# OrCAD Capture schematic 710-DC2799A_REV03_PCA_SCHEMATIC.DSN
size B; note: SPI Extender Over Differential Link
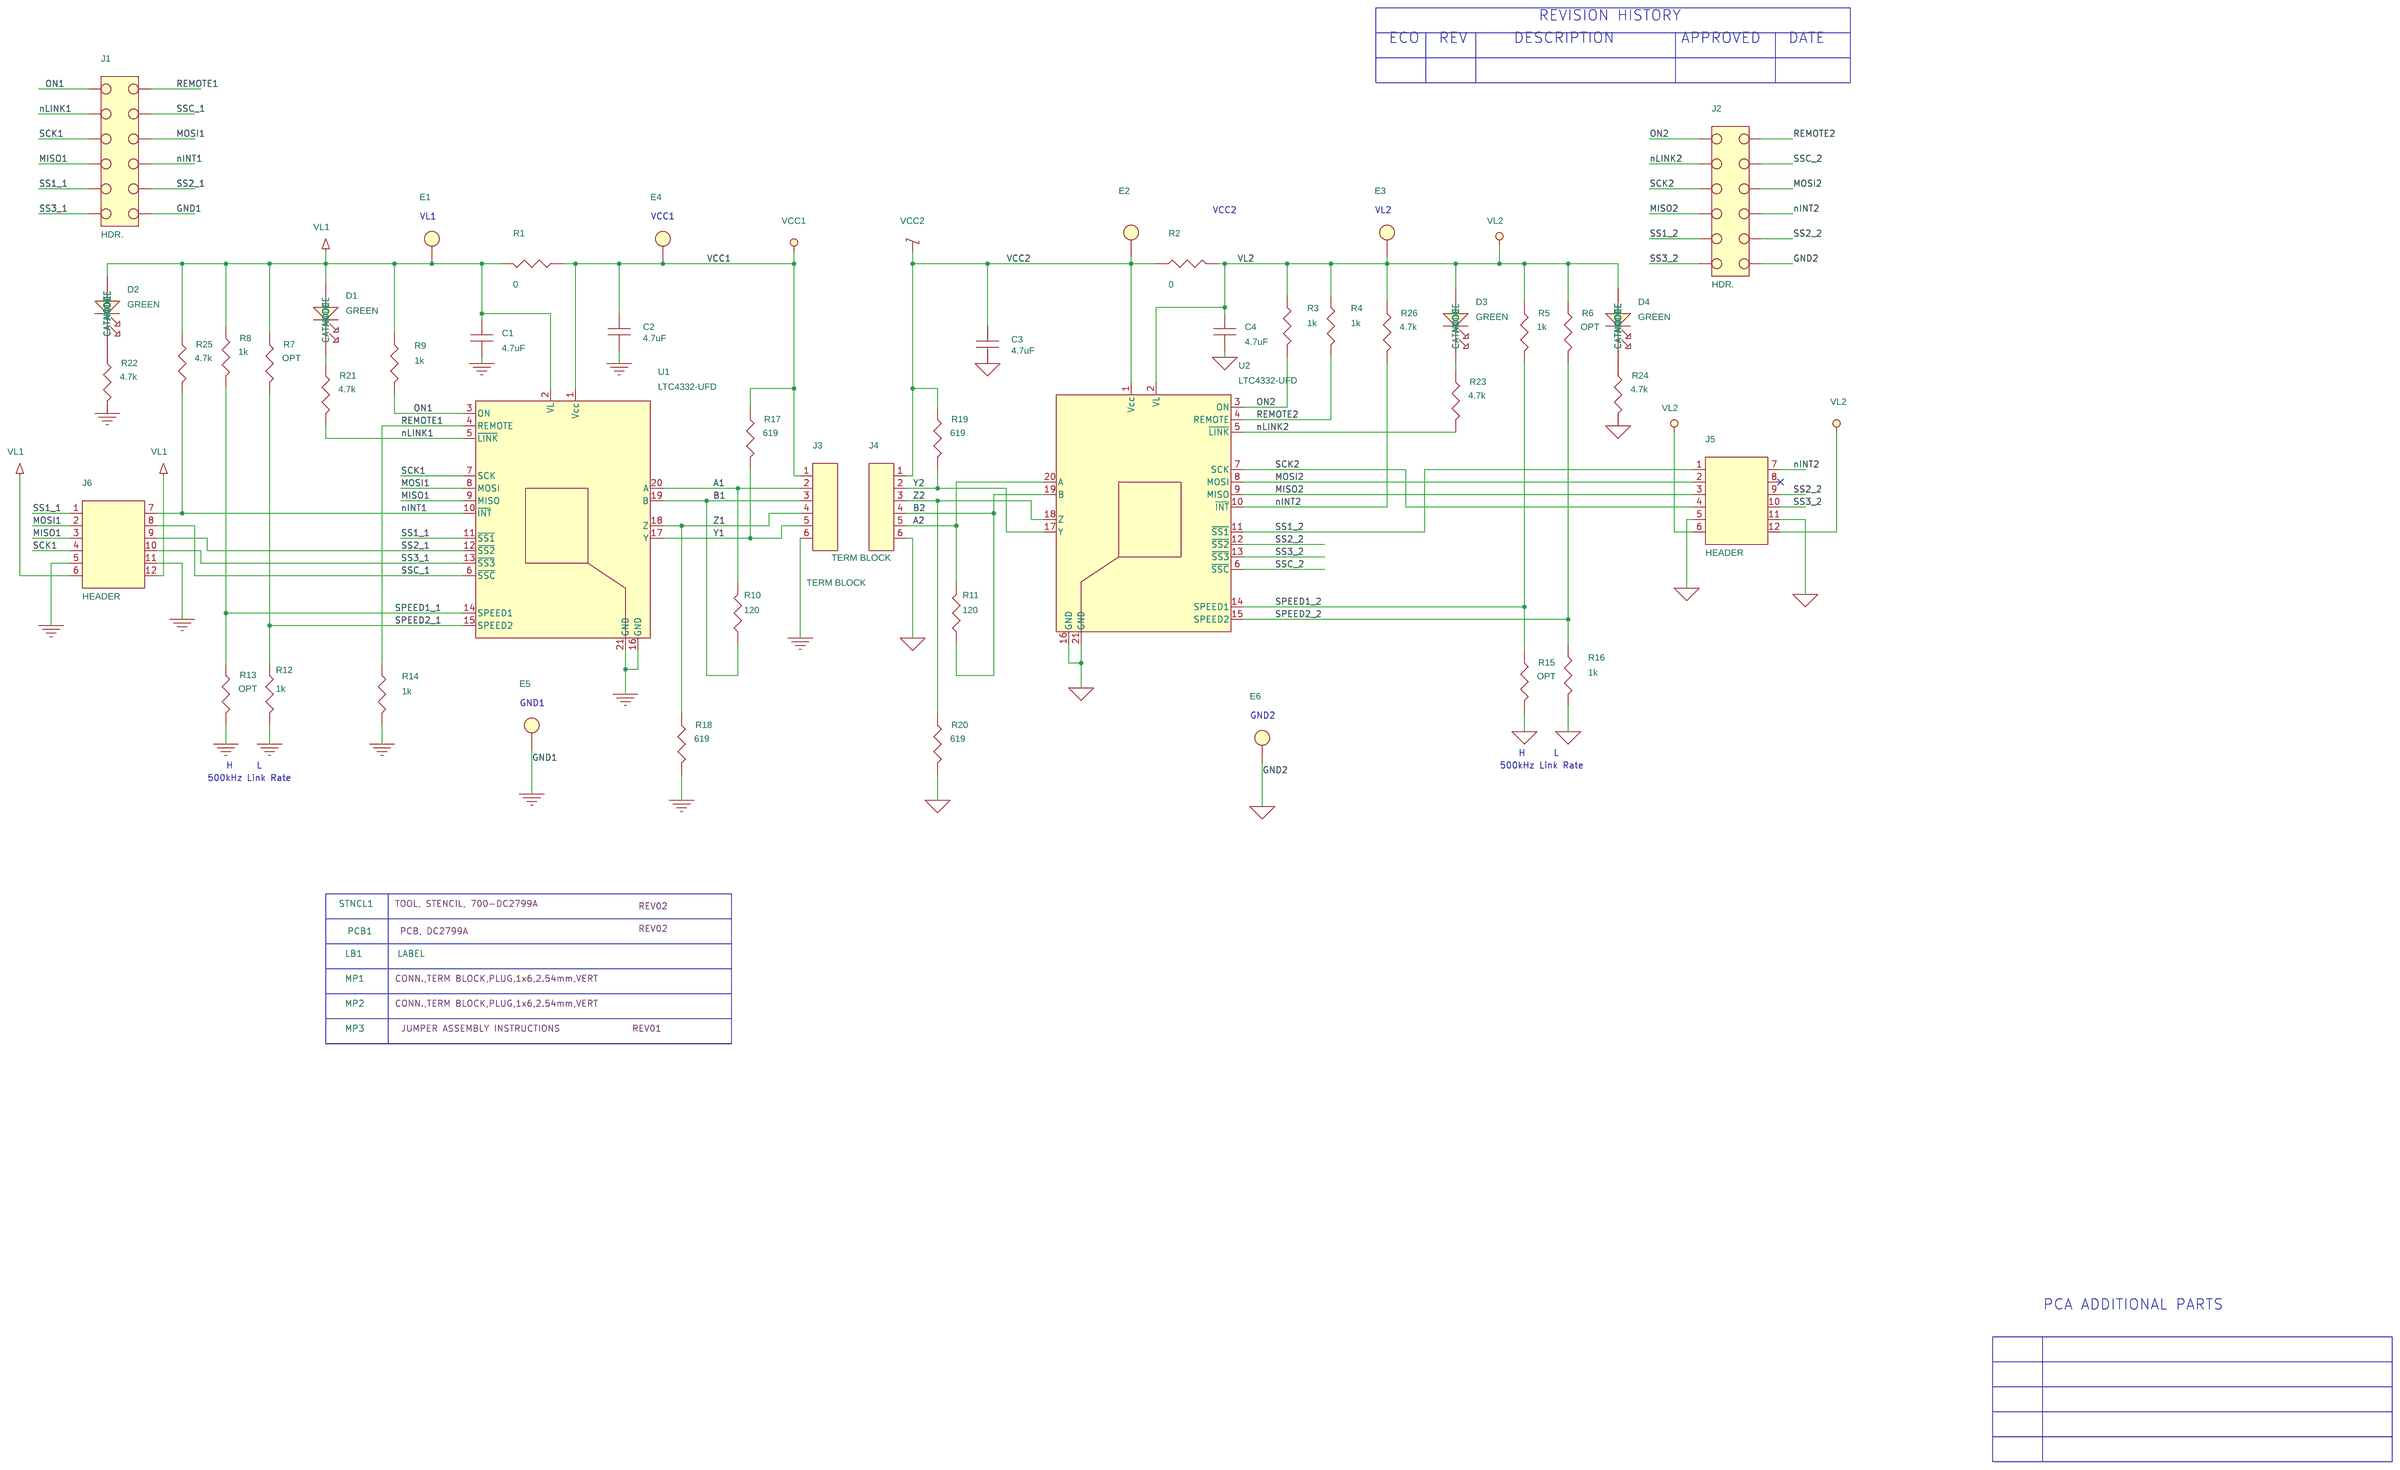
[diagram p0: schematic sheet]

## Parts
C1  4.7uF  [CC0603N]
C2  4.7uF  [CC0603N]
C3  4.7uF  [CC0603N]
C4  4.7uF  [CC0603N]
D1  GREEN  [LED_0603]
D2  GREEN  [LED_0603]
D3  GREEN  [LED_0603]
D4  GREEN  [LED_0603]
E1  TEST POINT  [MILLMAX2308]
E2  TEST POINT  [MILLMAX2308]
E3  TEST POINT  [MILLMAX2308]
E4  TEST POINT  [MILLMAX2308]
E5  TEST POINT  [MILLMAX2308]
E6  TEST POINT  [MILLMAX2308]
J1  HDR.  [HDR2X6-100-SM]
J2  HDR.  [HDR2X6-100-SM]
J3  TERM BLOCK  [WURTH-691382000006]
J4  TERM BLOCK  [WURTH-691382000006]
J5  HEADER  [WURTH-613012243121_PMOD]
J6  HEADER  [WURTH-61301221021_PMOD]
LB1  LABEL  [895-0154_REV01]
MP1  TERM BLOCK  [UNASSIGNED]
MP2  TERM BLOCK  [UNASSIGNED]
MP3  DOCUMENT
PCB1  PCB, DC2799A
R1  0  [CR0603N]
R2  0  [CR0603N]
R3  1k  [CR0805N]
R4  1k  [CR0805N]
R5  1k  [CR0805N]
R6  OPT  [CR0805N]
R7  OPT  [CR0805N]
R8  1k  [CR0805N]
R9  1k  [CR0805N]
R10  120  [CR0805N]
R11  120  [CR0805N]
R12  1k  [CR0805N]
R13  OPT  [CR0805N]
R14  1k  [CR0805N]
R15  OPT  [CR0805N]
R16  1k  [CR0805N]
R17  619  [CR0805N]
R18  619  [CR0805N]
R19  619  [CR0805N]
R20  619  [CR0805N]
R21  4.7k  [CR0603N]
R22  4.7k  [CR0603N]
R23  4.7k  [CR0603N]
R24  4.7k  [CR0603N]
R25  4.7k  [CR0603N]
R26  4.7k  [CR0603N]
STNCL1  TOOL, STENCIL, 700-DC2799A
U1  LTC4332-UFD  [LTC-UFD-20-1711]
U2  LTC4332-UFD  [LTC-UFD-20-1711]

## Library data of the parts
C1 C4 = CAP: CAP.,4.7uF,X5R,16V,20%,0603; CLASS: DISCRETE; Dielectric Type: X5R; FPLIST: CC0603N,CC0603L,CC0603M; Inventory Qty: 28841; Manufacturer: MURATA; Manufacturer PN: GRM188R61C475MAAJD; PART_NUMBER: 150-0551; Package Size: 0603; Rated Voltage: 16V; Tolerance: 20%
C2 C3 = CAP: CAP.,4.7uF,X5R,16V,20%,0603; CLASS: DISCRETE; Dielectric Type: X5R; FPLIST: CC0603N,CC0603L,CC0603M; Inventory Qty: 28841; Manufacturer: MURATA; Manufacturer PN: GRM188R61C475MAAJD; PART_NUMBER: 150-0551; Package Size: 0603; Rated Voltage: 16V; Tolerance: 20%; UserField01: AEC-Q200
D1-D4 = LED: LED,GREEN,WATERCLEAR,0603; CLASS: DISCRETE; Inventory Qty: 7311; Manufacturer: WURTH ELEKTRONIK; Manufacturer PN: 150060GS75000; PART_NUMBER: 270-0057; Package Type: 0603
E1-E6 = TEST_POINT_.156_MILL-MAX_2308: TEST POINT,TURRET,0.064" MTG. HOLE,PCB 0.062" THICK; CLASS: IO; Inventory Qty: 833448; Manufacturer: MILL-MAX; Manufacturer PN: 2308-2-00-80-00-00-07-0; PART_NUMBER: 260-0004
J1 J2 = HDR2X6: CONN.,HDR.,MALE,2x6,2.54mm,THT, STR; CLASS: IO; Inventory Qty: 1000; Manufacturer: SAMTEC; Manufacturer PN: TSW-106-07-S-D; PART_NUMBER: 250-0740
J3 J4 = CON6: CONN.,TERM BLOCK,HEADER,1x6,2.54mm,VERT; CLASS: IO; Inventory Qty: 0; Manufacturer: WURTH ELEKTRONIK; Manufacturer PN: 691382000006; PART_NUMBER: 250-0924
J5 = HDR2x6_PMOD: CONN.,HEADER,RECEPT,2x6,.100",2.54mm,TH,R/A; CLASS: IO; FPLIST: WURTH-613012243121,WURTH-613012243121_PMOD; Inventory Qty: 0; Manufacturer: Sullins Connector Solutions; Manufacturer PN: PPPC062LJBN-RC; Operating Temperature Minimum: -40C - 105C; PART_NUMBER: 250-0925
J6 = HDR2x6_PMOD: CONN.,HEADER,MALE,2x6,2.54mm,TH,R/A; CLASS: IO; FPLIST: WURTH-61301221021,WURTH-61301221021_PMOD; Inventory Qty: 0; Manufacturer: WURTH ELEKTRONIK; Manufacturer PN: 61301221021; Operating Temperature Minimum: -40C - 125C; PART_NUMBER: 250-0926
LB1 = BLANK_LABEL: LABEL SPEC, DEMO BOARD SERIAL NUMBER; Inventory Qty: 0; Manufacturer: BRADY; Manufacturer PN: THT-96-717-10; PART_NUMBER: 895-0154
MP1 MP2 = BLANK_PINLESS_MECHANICAL_PART: CONN.,TERM BLOCK,PLUG,1x6,2.54mm,VERT; CLASS: IO; Inventory Qty: 0; Manufacturer: WURTH ELEKTRONIK; Manufacturer PN: 691381000006; PART_NUMBER: 250-0923
MP3 = BLANK_PINLESS_MECHANICAL_PART: JUMPER ASSEMBLY INSTRUCTIONS; BOM Notes: REV01; CLASS: DISCRETE; Manufacturer: ANALOG DEVICES INC.; Manufacturer PN: 003-0102; PART_NUMBER: 003-0102
PCB1 = BLANK_PCB_PART: BOM Notes: REV02; CLASS: DISCRETE; Inventory Qty: 0; Manufacturer: EAGLE TECH. INC.; Manufacturer PN: 600-DC2799A; PART_NUMBER: 600-DC2799A
R1 R2 = RES: RES.,0 OHM,1/10W,0603,AEC-Q200; CLASS: DISCRETE; FPLIST: CR0603N,CR0603L,CR0603M; Inventory Qty: 642761; Manufacturer: VISHAY; Manufacturer PN: CRCW06030000Z0EA; PART_NUMBER: 100-0009; Package Size: 0603; Rated Power: 1/10W
R3-R5 R8 R9 R12 R14 R16 = RES: RES.,1k OHMS,1%,1/8W,0805,AEC-Q200; CLASS: DISCRETE; FPLIST: CR0805N,CR0805L,CR0805M; Inventory Qty: 20150; Manufacturer: PANASONIC; Manufacturer PN: ERJ-6ENF1001V; PART_NUMBER: 100-0761; Package Size: 0805; Rated Power: 1/8W; Temperature Coefficient: +/-100PPM; Tolerance: 1%
R6 R7 R13 R15 = RES: RES., OPTION, 0805; CLASS: DISCRETE; FPLIST: CR0805N,CR0805L,CR0805M; PART_NUMBER: 100-2558; Package Size: 0805
R10 R11 = RES: RES.,120 OHMS,5%,1/8W,0805,AEC-Q200; CLASS: DISCRETE; FPLIST: CR0805N,CR0805L,CR0805M; Inventory Qty: 9960; Manufacturer: NIC; Manufacturer PN: NRC10J121TRF; PART_NUMBER: 100-0132; Package Size: 0805; Rated Power: 1/8W; Temperature Coefficient: 200ppm/C; Tolerance: 5%
R17-R20 = RES: RES.,619 OHMS,1%,1/8W,0805,AEC-Q200; CLASS: DISCRETE; FPLIST: CR0805N,CR0805L,CR0805M; Inventory Qty: 4920; Manufacturer: NIC; Manufacturer PN: NRC10F6190TRF; PART_NUMBER: 100-0931; Package Size: 0805; Rated Power: 1/8W; Temperature Coefficient: +/-100PPM; Tolerance: 1%
R21-R26 = RES: RES.,4.7k OHMS,1%,1/10W,0603,AEC-Q200; CLASS: DISCRETE; FPLIST: CR0603N,CR0603L,CR0603M; Inventory Qty: 5995; Manufacturer: NIC; Manufacturer PN: NRC06F4701TRF; PART_NUMBER: 100-2743; Package Size: 0603; Rated Power: 1/10W; Temperature Coefficient: 100ppm/C; Tolerance: 1%
STNCL1 = BLANK_STENCIL_PART: BOM Notes: REV02; CLASS: DISCRETE; Inventory Qty: 0; Manufacturer: LINEAR TECH.; Manufacturer PN: 830-DC2799A; PART_NUMBER: 830-DC2799A
U1 U2 = LTC4332-UFD: IC,RUGGED SPI EXTENDER,QFN-20; CLASS: IC; Inventory Qty: 0; Manufacturer: LINEAR TECH.; Manufacturer PN: LTC4332CUFD#PBF; PART_NUMBER: LTC4332CUFD#PBF; Package Size: LTC-UFD20; Package Type: QFN-20

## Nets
GND: C1.2 C2.2 E5.1(A) J1.12 J3.6 J6.5 J6.11 R12.2 R13.2 R14.2 R18.2 R22.2 U1.16(GND) U1.21(GND)
GND_SIGNAL: C3.2 C4.2 E6.1(A) J2.12 J4.6 J5.5 J5.11 R15.2 R16.2 R20.2 R24.2 U2.16(GND) U2.21(GND)
VCC1: C2.1 E4.1(A) J3.1 R1.1 R17.1 U1.1(Vcc)
VCC2: C3.1 E2.1(A) J4.1 R2.1 R19.1 U2.1(Vcc)
A1: J3.2 R10.2 U1.20(A)
A2: J4.5 R11.2 U2.20(A)
B1: J3.3 R10.1 U1.19(B)
B2: J4.4 R11.1 U2.19(B)
MISO1: J1.7 J6.3 U1.9(MISO)
MISO2: J2.7 J5.3 U2.9(MISO)
MOSI1: J1.6 J6.2 U1.8(MOSI)
MOSI2: J2.6 J5.2 U2.8(MOSI)
nINT1: J1.8 J6.7 R25.2 U1.10(~{INT})
nINT2: J2.8 J5.7 R26.2 U2.10(~{INT})
nLINK1: J1.3 R21.2 U1.5(~{LINK})
nLINK2: J2.3 R23.2 U2.5(~{LINK})
ON1: J1.1 R9.2 U1.3(ON)
ON2: J2.1 R3.2 U2.3(ON)
REMOTE1: J1.2 R14.1 U1.4(REMOTE)
REMOTE2: J2.2 R4.2 U2.4(REMOTE)
SCK1: J1.5 J6.4 U1.7(SCK)
SCK2: J2.5 J5.4 U2.7(SCK)
SPEED1_1: R8.2 R13.1 U1.14(SPEED1)
SPEED1_2: R5.2 R15.1 U2.14(SPEED1)
SPEED2_1: R7.2 R12.1 U1.15(SPEED2)
SPEED2_2: R6.2 R16.1 U2.15(SPEED2)
SS1_1: J1.9 J6.1 U1.11(~{SS1})
SS1_2: J2.9 J5.1 U2.11(~{SS1})
SS2_1: J1.10 J6.9 U1.12(~{SS2})
SS2_2: J2.10 J5.9 U2.12(~{SS2})
SS3_1: J1.11 J6.10 U1.13(~{SS3})
SS3_2: J2.11 J5.10 U2.13(~{SS3})
SSC_1: J1.4 J6.8 U1.6(~{SSC})
SSC_2: J2.4 U2.6(~{SSC})
VL1: C1.1 D1.2(ANODE) D2.2(ANODE) E1.1(A) J6.6 J6.12 R1.2 R7.1 R8.1 R9.1 R25.1 U1.2(VL)
VL2: C4.1 D3.2(ANODE) D4.2(ANODE) E3.1(A) J5.6 J5.12 R2.2 R3.1 R4.1 R5.1 R6.1 R26.1 U2.2(VL)
Y1: J3.5 R17.2 U1.17(Y)
Y2: J4.2 R19.2 U2.17(Y)
Z1: J3.4 R18.1 U1.18(Z)
Z2: J4.3 R20.1 U2.18(Z)
N1330778: D1.1(CATHODE) R21.1
N1332111: D3.1(CATHODE) R23.1
N1350356: D2.1(CATHODE) R22.1
N1350357: D4.1(CATHODE) R24.1

Not connected (* = marked no-connect by the designer): J5 8*

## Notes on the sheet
- REVISION HISTORY
- ECO
- REV
- DESCRIPTION
- APPROVED
- DATE
- VL1
- VCC1
- VCC2
- VL2
- GND1
- GND2
- H      L
- H     L
- 500kHz Link Rate
- 500kHz Link Rate
- PCA ADDITIONAL PARTS
